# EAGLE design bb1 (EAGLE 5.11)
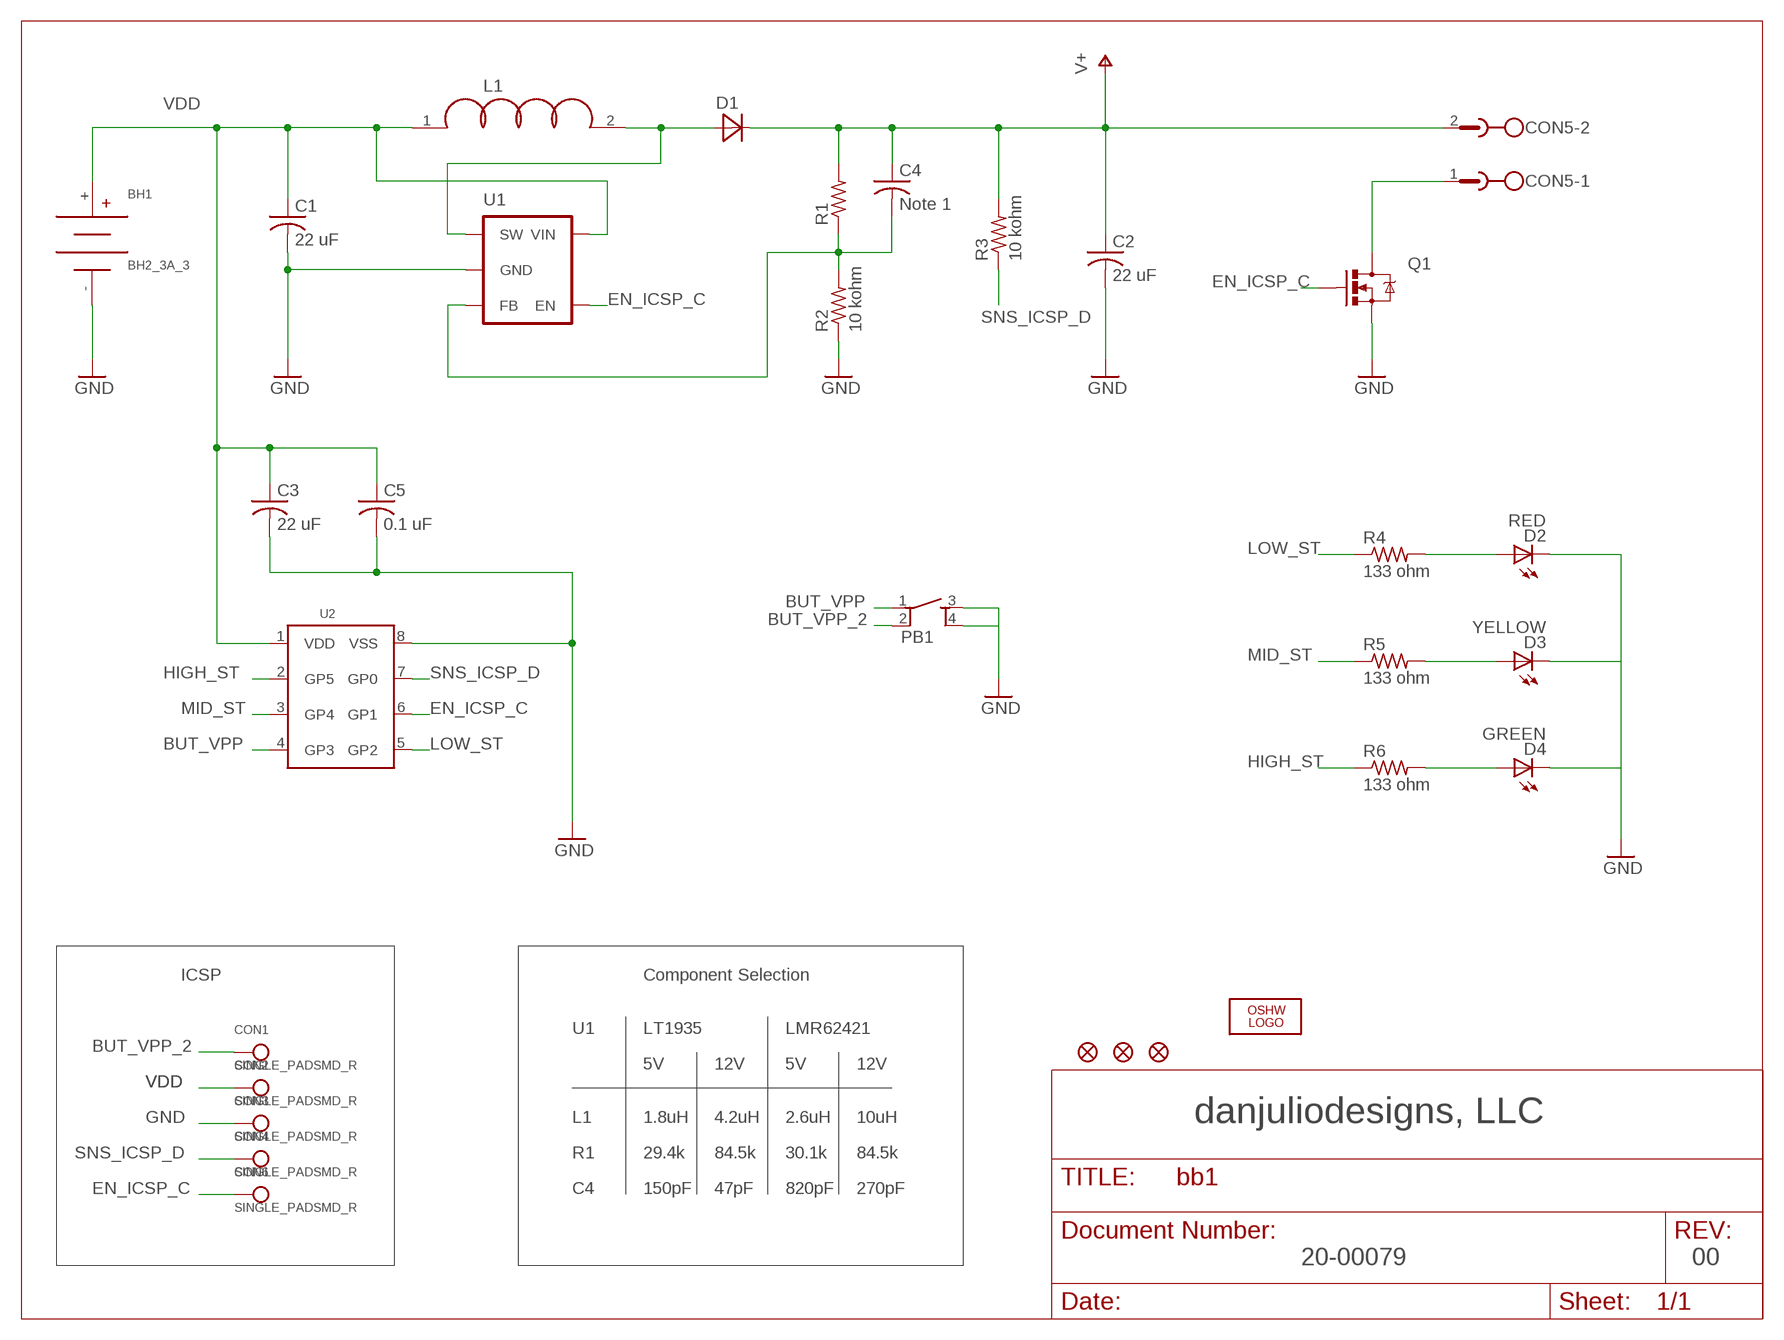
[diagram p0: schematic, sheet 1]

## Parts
BH1  BH2_3A_3  [BH2_3A_3]
C1  22 uF  C-USSMT1206  [C1206]
C2  22 uF  C-USSMT1206  [C1206]
C3  22 uF  C-USSMT1206  [C1206]
C4  Note 1  C-USSMT0603  [C0603]
C5  0.1 uF  C-USSMT0603  [C0603]
CON1  SINGLE_PADSMD_R  [2MM_R_SMD_PAD]
CON2  SINGLE_PADSMD_R  [2MM_R_SMD_PAD]
CON3  SINGLE_PADSMD_R  [2MM_R_SMD_PAD]
CON4  SINGLE_PADSMD_R  [2MM_R_SMD_PAD]
CON5  MKDSN2  [MKDSN2]
CON6  SINGLE_PADSMD_R  [2MM_R_SMD_PAD]
D1  DIODESMT_SOD123  [SOD123]
D2  RED  LEDSMT0805  [LED_0805]
D3  YELLOW  LEDSMT0805  [LED_0805]
D4  GREEN  LEDSMT0805  [LED_0805]
L1  INDUCTORSMT5_8X5_8  [IND_5_8X5_8]
LOGO1  OSHW_LOGO_8MILX0150-NT  [OSHW_8X150_NOTEXT]
PB1  PB_TACT_4SMTR92  [CK_PTS645_SMT]
Q1  MOSFET-NCHANNEL  [SOT23-3]
R1  R-USSMT0603  [R0603]
R2  10 kohm  R-USSMT0603  [R0603]
R3  10 kohm  R-USSMT0603  [R0603]
R4  133 ohm  R-USSMT0603  [R0603]
R5  133 ohm  R-USSMT0603  [R0603]
R6  133 ohm  R-USSMT0603  [R0603]
U1  LT1935  [SOT23-5]
U2  PIC12F609_615SO8  [SO8]
U$1  FIDUCIAL  [FIDUCIAL]
U$2  FIDUCIAL  [FIDUCIAL]
U$3  FIDUCIAL  [FIDUCIAL]

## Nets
BUT_VPP: PB1.1 U2.4(GP3)
BUT_VPP_2: CON1.P$1 PB1.2
EN_ICSP_C: CON6.P$1 Q1.1(G) U1.4(EN) U2.6(GP1)
GND: BH1.- C1.2 C2.2 C3.2 C5.2 CON3.P$1 D2.C D3.C D4.C PB1.3 PB1.4 Q1.2(S) R2.1 U1.2(GND) U2.8(VSS)
HIGH_ST: R6.1 U2.2(GP5)
LOW_ST: R4.1 U2.5(GP2)
MID_ST: R5.1 U2.3(GP4)
N$1: D3.A R5.2
N$2: D4.A R6.2
N$3: D1.A L1.2 U1.1(SW)
N$4: CON5.1 Q1.3(D)
N$5: C4.2 R1.1 R2.2 U1.3(FB)
N$7: D2.A R4.2
SNS_ICSP_D: CON4.P$1 R3.1 U2.7(GP0)
V+: C2.1 C4.1 CON5.2 D1.C R1.2 R3.2
VDD: BH1.+ C1.1 C3.1 C5.1 CON2.P$1 L1.1 U1.5(VIN) U2.1(VDD)

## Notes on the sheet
- ICSP | Component Selection
- U1 | LT1935 | LMR62421
- 5V | 12V | 5V | 12V
- L1 | 1.8uH | 4.2uH | 2.6uH | 10uH | danjuliodesigns, LLC
- R1 | 29.4k | 84.5k | 30.1k | 84.5k
- C4 | 150pF | 47pF | 820pF | 270pF
- 20-00079 | 00

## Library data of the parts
BH1 = djd_eagle_library:BH2_3A_3
C1-C5 = djd_eagle_library:C-US
CON1-CON4 CON6 = djd_eagle_library:SINGLE_PAD
CON5 = djd_eagle_library:MKDSN2
D1 = djd_eagle_library:DIODE
D2-D4 = djd_eagle_library:LED
L1 = djd_eagle_library:INDUCTOR
LOGO1 = ohw-logo:OSHW_LOGO_8MIL
PB1 = djd_eagle_library:PB_TACT_4: Common 4-pin Tact Button
Q1 = djd_eagle_library:MOSFET-NCHANNEL
R1-R6 = djd_eagle_library:R-US
U1 = djd_eagle_library:LT1935
U2 = djd_eagle_library:PIC12F609_615
U$1-U$3 = djd_eagle_library:FIDUCIAL

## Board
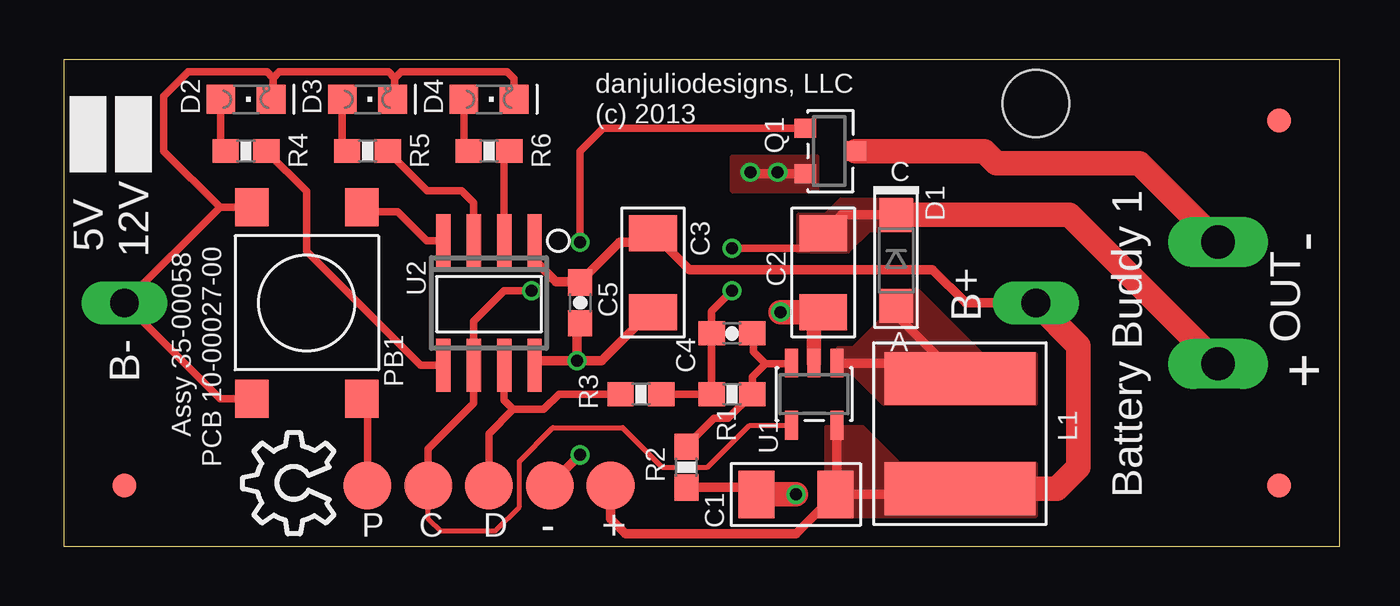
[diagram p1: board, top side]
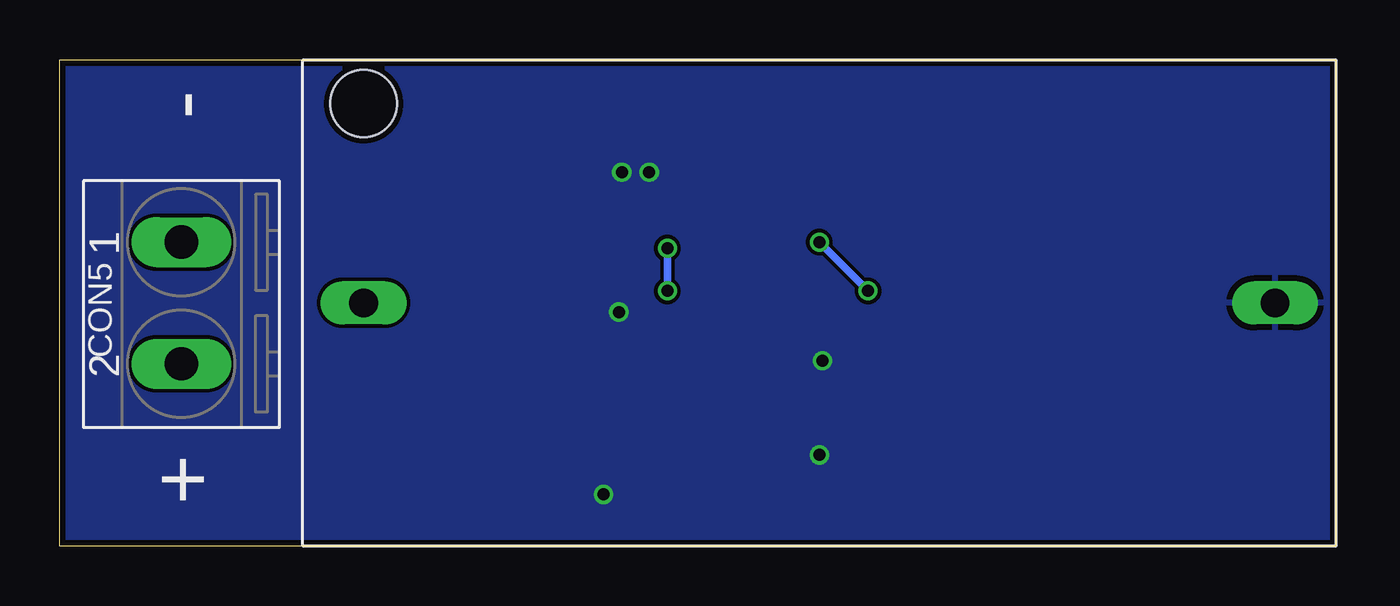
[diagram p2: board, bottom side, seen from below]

Size 53.34 x 20.32 mm. Coordinates in mm from the lower left corner, seen from the top.
Outline: 0,0 53.34,0 53.34,20.32 0,20.32 0,0
Copper layers (1*16): Top 0.035mm / dielectric 1.5mm / Bottom 0.035mm
Design rules "ITead_rule": minimum track width 6mil, minimum drill 12mil, track to track 6mil, track to pad 6mil, pad to pad 6mil, via to via 6mil, smd to smd 0mil, copper to edge 10mil, drill to drill 10mil, minimum pad ring 10mil, minimum via ring 6mil, stop-mask expansion 2mil, vias tented up to drill 100mil, thermal gap 10mil

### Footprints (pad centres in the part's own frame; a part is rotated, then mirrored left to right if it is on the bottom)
BH2_3A_3 = drill 1.2 long: + 19.05,0; - -19.05,0 | hole 2.8: 19.05,-8.331
C1206 = smd 2 x 1.5: 1 0,-1.65; 2 0,1.65
C0603 = smd 1.1 x 1: 1 -0.85,0; 2 0.85,0
2MM_R_SMD_PAD = smd 2 x 2: P$1 0,0
MKDSN2 = drill 1.397 long: 1 -2.54,0; 2 2.54,0
SOD123 = smd 1.4 x 1.4: A 1.9,0; C -1.9,0
LED_0805 = smd 1.2 x 1.2: A 0,-1.05; C 0,1.05
IND_5_8X5_8 = smd 6.3 x 2.2: 1 0,2.3; 2 0,-2.3
CK_PTS645_SMT = smd 1.6 x 1.4: 1 -4,2.3; 2 4,2.3; 3 -4,-2.3; 4 4,-2.3
SOT23-3 = smd 0.8 x 0.9: 1 -0.95,-1; 2 0.95,-1; 3 0,1.1
R0603 = smd 1.1 x 1: 1 -0.85,0; 2 0.85,0
SOT23-5 = smd 0.55 x 1.2: 1 -0.95,-1.3; 2 0,-1.3; 3 0.95,-1.3; 4 0.95,1.3; 5 -0.95,1.3
SO8 = smd 0.6 x 2.2: 1 -1.905,-2.6; 2 -0.635,-2.6; 3 0.635,-2.6; 4 1.905,-2.6; 5 1.905,2.6; 6 0.635,2.6; 7 -0.635,2.6; 8 -1.905,2.6
FIDUCIAL = smd 1 x 1: 1 0,0

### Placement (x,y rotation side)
BH1  21.59,10.16 180 bottom
C1  30.61,2.16 90 top
C2  31.75,11.43 180 top
C3  24.64,11.43 180 top
C4  27.94,8.89 0 top
C5  21.59,10.16 270 top
CON1  12.7,2.54 0 top
CON2  22.86,2.54 0 top
CON3  20.32,2.54 0 top
CON4  17.78,2.54 0 top
CON5  48.26,10.16 270 bottom
CON6  15.24,2.54 0 top
D1  34.8,11.94 270 top
D2  7.62,18.67 270 top
D3  12.7,18.67 270 top
D4  17.78,18.67 270 top
L1  37.47,4.7 180 top
LOGO1  11.3,0.51 90 top
PB1  10.16,10.16 270 top
Q1  32,16.51 270 top
R1  27.94,6.35 180 top
R2  26.04,3.3 90 top
R3  24.13,6.35 0 top
R4  7.62,16.51 180 top
R5  12.7,16.51 180 top
R6  17.78,16.51 180 top
U1  31.37,6.35 180 top
U2  17.78,10.16 180 top
U$1  2.54,2.54 0 top
U$2  50.8,2.54 0 top
U$3  50.8,17.78 0 top

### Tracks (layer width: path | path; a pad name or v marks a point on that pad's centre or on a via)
BUT_VPP
  Top 0.305: U2.4 15.18,12.76 13.97,13.97 12.65,13.97 PB1.1
BUT_VPP_2
  Top 0.305: CON1.P$1 12.7,5.92 PB1.2
EN_ICSP_C  (via drill 0.5)
  Top 0.203: U1.4 28.67,5.05 26.92,3.3 25.02,3.3 23.37,4.95 20.45,4.95 19.05,3.56 19.05,1.65 18.03,0.64 15.75,0.64 15.24,1.14 CON6.P$1
  Top 0.305: CON6.P$1 15.24,4.06 17.14,5.97 U2.6 17.14,9.4 18.41,10.67 v19.56,10.67 | Q1.1 22.54,17.46 21.59,16.51 v21.59,12.7
  Bottom 0.305: v19.56,10.67 v21.59,12.7
GND  (via drill 0.5)
  Top 0.305: PB1.4 6.54,6.16 BH1.- 6.54,14.16 | 6.54,14.16 PB1.3 | D4.C 18.83,19.52 18.54,19.81 14.1,19.81 13.84,19.56 | 13.84,19.56 13.59,19.81 9.02,19.81 8.76,19.56 | 8.76,19.56 8.51,19.81 5.21,19.81 4.19,18.8 4.19,16.51 6.54,14.16 | 8.76,19.56 8.76,18.76 D2.C | 13.84,19.56 13.84,18.76 D3.C
  Top 0.406: R2.1 28.66,2.45 C1.2 | CON3.P$1 v21.59,3.81 | v21.46,7.75 19.87,7.75 U2.8 | v21.46,7.75 21.46,9.18 C5.2 | C3.2 24.51,9.78 22.48,7.75 v21.46,7.75 | Q1.2 28.83,15.56 v28.7,15.62
  Top 0.61: U1.2 31.37,9.4 C2.2
  Top 1.016: C1.2 v30.61,2.16 | C2.2 v29.97,9.78
  other vias: 29.84,15.62
  pour Bottom: 0,20.32 53.34,20.32 53.34,0 0,0
  pour Top (no thermals): 31.5,14.86 31.5,16.26 27.94,16.26 27.94,14.86
HIGH_ST
  Top 0.305: U2.2 18.41,16.3 R6.1
LOW_ST
  Top 0.305: U2.5 14.92,7.56 10.16,12.32 10.16,14.82 R4.1
MID_ST
  Top 0.305: U2.3 17.14,14.35 16.64,14.86 15.2,14.86 R5.1
N$1
  Top 0.305: D3.A 11.65,16.71 R5.2
N$2
  Top 0.305: D4.A 16.73,16.71 R6.2
N$3
  Top 0.406: D1.A 34.8,9.67 L1.2 36.81,7.65 U1.1
  pour Top (no thermals): 32.38,7.24 33.02,7.24 34.29,5.97 40.64,5.97 40.64,8 38.35,8 35.69,10.67 34.16,10.67 34.16,9.4 33.02,8.26 32.38,8.26
N$4
  Top 1.016: Q1.3 38.48,16.51 38.99,16 44.96,16 CON5.1
N$5
  Top 0.305: R2.2 26.04,4.19 27.18,5.33 27.77,5.33 R1.1 28.79,7.07 29.34,7.62 | 29.34,7.62 28.83,8.13 28.83,8.85 C4.2 | 29.34,7.62 30.39,7.62 U1.3
N$7
  Top 0.305: D2.A 6.57,16.71 R4.2
SNS_ICSP_D
  Top 0.305: U2.7 18.41,6.1 18.8,5.71 | 18.8,5.71 17.78,4.7 CON4.P$1 | R3.1 20.7,6.35 20.07,5.71 18.8,5.71
V+  (via drill 0.5)
  Top 0.305: R3.2 R1.2 C4.1 27.09,9.82 v27.94,10.67 | v27.94,12.45 31.11,12.45 C2.1
  Top 0.406: D1.C 32.51,13.84 C2.1
  Top 1.016: D1.C 42.04,13.84 CON5.2
  Bottom 0.305: v27.94,10.67 v27.94,12.45
  pour Top (no thermals): 35.43,13.21 33.66,13.21 32.77,12.32 30.73,12.32 30.73,13.84 31.88,13.84 32.51,14.48 35.43,14.48
VDD
  Top 0.406: CON2.P$1 22.86,1.14 23.5,0.51 30.61,0.51 C1.1 | BH1.+ 37.72,10.16 36.32,11.56 26.16,11.56 C3.1 24.26,12.7 23.24,12.7 21.59,11.05 C5.1 21.55,11.05 20.57,11.05 19.68,11.94 U2.1 | C1.1 37.23,2.16 L1.1 | U1.5 32.32,2.22 C1.1
  Top 1.016: L1.1 41.52,2.4 42.42,3.3 42.42,8.38 BH1.+
  pour Top (no thermals): 31.88,4.95 31.88,1.27 40.64,1.27 40.64,3.43 34.92,3.43 33.4,4.95

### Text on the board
tPlace: danjuliodesigns, LLC | (c) 2013 | 5V | 12V | - | B+ | OUT | B- | + | Assy 35-00058 | PCB 10-00027-00 | Battery Buddy 1 | P | C | D | - | +
bPlace: - | +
